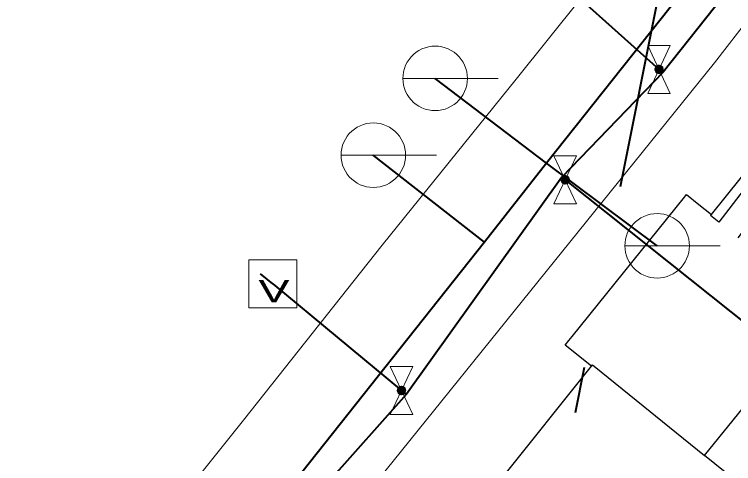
# Model space of a CAD drawing. Extents: x -968691 to -140888, y -1376050 to -879856.
# Drawn here: x -646150.75 to -646128.3, y -1062525.12 to -1062511.09 of the extents above; entities that cross this region are included whole.
import ezdxf
from ezdxf.enums import TextEntityAlignment as Align

# ---------------------------------------------------------------- set-up
doc = ezdxf.new("R2010")
doc.units = 0
doc.header["$LTSCALE"] = 4.8
for name, pattern in [('DASH_DOUBLE_DOT', [9.2, 5, -1.2, 0.3, -1.2, 0.3, -1.2]), ('DOTTED', [1.5, 0.3, -1.2]), ('LONG_DASHED', [7.5, 6, -1.5]), ('MEDIUM_DASHED', [4.5, 3, -1.5])]:
    doc.linetypes.add(name, pattern=pattern)
doc.layers.add('1', color=7, linetype='Continuous', lineweight=13)

msp = doc.modelspace()

# ---------------------------------------------------------------- hatches: boundary and pattern name
at = {"layer": '1'}
for points in [[(-646130.498, -1062512.81), (-646130.5, -1062512.786), (-646130.507, -1062512.763), (-646130.517, -1062512.741), (-646130.531, -1062512.722), (-646130.549, -1062512.705), (-646130.569, -1062512.692), (-646130.592, -1062512.683), (-646130.615, -1062512.679), (-646130.639, -1062512.678), (-646130.663, -1062512.682), (-646130.686, -1062512.69), (-646130.707, -1062512.702), (-646130.725, -1062512.718), (-646130.74, -1062512.737), (-646130.752, -1062512.758), (-646130.759, -1062512.781), (-646130.762, -1062512.805), (-646130.761, -1062512.829), (-646130.755, -1062512.852), (-646130.745, -1062512.874), (-646130.732, -1062512.894), (-646130.715, -1062512.911), (-646130.695, -1062512.925), (-646130.673, -1062512.935), (-646130.65, -1062512.941), (-646130.626, -1062512.942), (-646130.602, -1062512.939), (-646130.579, -1062512.932), (-646130.558, -1062512.921), (-646130.539, -1062512.906), (-646130.523, -1062512.887), (-646130.511, -1062512.867), (-646130.502, -1062512.844), (-646130.498, -1062512.82)], [(-646133.428, -1062516.26), (-646133.43, -1062516.236), (-646133.437, -1062516.213), (-646133.447, -1062516.191), (-646133.461, -1062516.172), (-646133.479, -1062516.155), (-646133.499, -1062516.142), (-646133.522, -1062516.133), (-646133.545, -1062516.129), (-646133.569, -1062516.128), (-646133.593, -1062516.132), (-646133.616, -1062516.14), (-646133.637, -1062516.152), (-646133.655, -1062516.168), (-646133.67, -1062516.187), (-646133.682, -1062516.208), (-646133.689, -1062516.231), (-646133.692, -1062516.255), (-646133.691, -1062516.279), (-646133.685, -1062516.302), (-646133.675, -1062516.324), (-646133.662, -1062516.344), (-646133.645, -1062516.361), (-646133.625, -1062516.375), (-646133.603, -1062516.385), (-646133.58, -1062516.391), (-646133.556, -1062516.392), (-646133.532, -1062516.389), (-646133.509, -1062516.382), (-646133.488, -1062516.371), (-646133.469, -1062516.356), (-646133.453, -1062516.337), (-646133.441, -1062516.317), (-646133.432, -1062516.294), (-646133.428, -1062516.27)], [(-646138.538, -1062522.84), (-646138.54, -1062522.816), (-646138.547, -1062522.793), (-646138.557, -1062522.771), (-646138.571, -1062522.752), (-646138.589, -1062522.735), (-646138.609, -1062522.722), (-646138.632, -1062522.713), (-646138.655, -1062522.709), (-646138.679, -1062522.708), (-646138.703, -1062522.712), (-646138.726, -1062522.72), (-646138.747, -1062522.732), (-646138.765, -1062522.748), (-646138.78, -1062522.767), (-646138.792, -1062522.788), (-646138.799, -1062522.811), (-646138.802, -1062522.835), (-646138.801, -1062522.859), (-646138.795, -1062522.882), (-646138.785, -1062522.904), (-646138.772, -1062522.924), (-646138.755, -1062522.941), (-646138.735, -1062522.955), (-646138.713, -1062522.965), (-646138.69, -1062522.971), (-646138.666, -1062522.972), (-646138.642, -1062522.969), (-646138.619, -1062522.962), (-646138.598, -1062522.951), (-646138.579, -1062522.936), (-646138.563, -1062522.917), (-646138.551, -1062522.897), (-646138.542, -1062522.874), (-646138.538, -1062522.85)]]:
    msp.add_hatch(color=256, dxfattribs=at).paths.add_polyline_path(points)

# ---------------------------------------------------------------- linework, layer by layer
for p, q in [((-646135.09, -1062513.113), (-646120.7, -1062495.06)), ((-646128.903, -1062512.606), (-646125.112, -1062507.701)), ((-646134.64, -1062509.22), (-646130.63, -1062512.81)), ((-646140.11, -1062526.51), (-646128.903, -1062512.606)), ((-646130.5, -1062512.9), (-646130.63, -1062512.81)), ((-646138.628, -1062513.09), (-646135.652, -1062513.09)), ((-646134.145, -1062515.74), (-646137.62, -1062513.09)), ((-646140.558, -1062515.49), (-646137.582, -1062515.49)), ((-646136.081, -1062518.202), (-646139.55, -1062515.49)), ((-646130.69, -1062518.32), (-646134.145, -1062515.74)), ((-646133.66, -1062516.18), (-646133.56, -1062516.26)), ((-646133.56, -1062516.26), (-646126.607, -1062521.806)), ((-646131.698, -1062518.32), (-646128.722, -1062518.32)), ((-646142.69, -1062519.51), (-646143.075, -1062519.191)), ((-646142.69, -1062519.51), (-646138.67, -1062522.84)), ((-646138.51, -1062522.95), (-646138.67, -1062522.84)), ((-646150.754, -1062532.695), (-646143.6, -1062523.77))]:
    msp.add_line(p, q, dxfattribs=at)
at = {"layer": '1', "linetype": 'DASH_DOUBLE_DOT', "lineweight": 40}
msp.add_line((-646149.08, -1062603.085), (-646128.34, -1062498.95), dxfattribs=at)
at = {"layer": '1', "linetype": 'LONG_DASHED', "lineweight": 40}
for p, q in [((-646124.36, -1062505.11), (-646130.5, -1062512.9)), ((-646134.64, -1062509.22), (-646130.63, -1062512.81)), ((-646130.5, -1062512.9), (-646133.66, -1062516.18)), ((-646130.5, -1062512.9), (-646130.63, -1062512.81)), ((-646134.145, -1062515.74), (-646137.62, -1062513.09)), ((-646136.081, -1062518.202), (-646139.55, -1062515.49)), ((-646130.69, -1062518.32), (-646134.145, -1062515.74)), ((-646133.66, -1062516.18), (-646138.51, -1062522.95)), ((-646133.66, -1062516.18), (-646133.56, -1062516.26)), ((-646133.56, -1062516.26), (-646126.607, -1062521.806)), ((-646142.69, -1062519.51), (-646138.67, -1062522.84)), ((-646138.51, -1062522.95), (-646138.67, -1062522.84)), ((-646138.51, -1062522.95), (-646141.97, -1062526.84))]:
    msp.add_line(p, q, dxfattribs=at)
at = {"layer": '1', "lineweight": 35}
for p, q in [((-646124.36, -1062505.11), (-646130.5, -1062512.9)), ((-646130.5, -1062512.9), (-646133.66, -1062516.18)), ((-646133.66, -1062516.18), (-646138.51, -1062522.95)), ((-646138.51, -1062522.95), (-646141.97, -1062526.84))]:
    msp.add_line(p, q, dxfattribs=at)
at = {"layer": '1', "linetype": 'MEDIUM_DASHED', "lineweight": 25}
for p, q in [((-646129.839, -1062516.805), (-646129.77, -1062516.72)), ((-646129.77, -1062516.72), (-646129.388, -1062517.026)), ((-646129.388, -1062517.026), (-646128.996, -1062517.34)), ((-646132.738, -1062522.076), (-646133.56, -1062521.42))]:
    msp.add_line(p, q, dxfattribs=at)
at = {"layer": '1', "linetype": 'DOTTED', "lineweight": 40}
msp.add_line((-646142.69, -1062519.51), (-646143.075, -1062519.191), dxfattribs=at)
at = {"layer": '1', "lineweight": 25}
for p, q in [((-646137.711, -1062528.301), (-646132.738, -1062522.076)), ((-646132.738, -1062522.076), (-646132.71, -1062522.04)), ((-646132.71, -1062522.04), (-646132.441, -1062522.257)), ((-646132.441, -1062522.257), (-646129.21, -1062524.87))]:
    msp.add_line(p, q, dxfattribs=at)
at = {"layer": '1', "linetype": 'LONG_DASHED', "lineweight": 40}
msp.add_lwpolyline([(-646125.463, -1062504.79), (-646134.145, -1062515.74), (-646136.081, -1062518.202), (-646142.83, -1062526.728), (-646149.07, -1062534.61)], dxfattribs=at)
at = {"layer": '1', "lineweight": 35}
msp.add_lwpolyline([(-646125.463, -1062504.79), (-646134.145, -1062515.74), (-646136.081, -1062518.202), (-646142.83, -1062526.728), (-646149.07, -1062534.61)], dxfattribs=at)
at = {"layer": '1', "lineweight": 25}
for points in [[(-646128.16, -1062518.07), (-646127.4, -1062517.07), (-646128, -1062516.59), (-646128.76, -1062517.58), (-646129.02, -1062517.37), (-646128.996, -1062517.34), (-646126.74, -1062514.527), (-646124.033, -1062511.151), (-646124, -1062511.11)], [(-646124.91, -1062528.34), (-646129.21, -1062524.87), (-646125.45, -1062520.24)]]:
    msp.add_lwpolyline(points, dxfattribs=at)
at = {"layer": '1'}
for points in [[(-646130.98, -1062512.06), (-646130.28, -1062512.06), (-646130.98, -1062513.56), (-646130.28, -1062513.56)], [(-646137.62, -1062512.082), (-646137.725, -1062512.088), (-646137.829, -1062512.104), (-646137.931, -1062512.132), (-646138.03, -1062512.17), (-646138.124, -1062512.217), (-646138.212, -1062512.275), (-646138.294, -1062512.341), (-646138.369, -1062512.416), (-646138.435, -1062512.498), (-646138.493, -1062512.586), (-646138.54, -1062512.68), (-646138.578, -1062512.779), (-646138.606, -1062512.881), (-646138.622, -1062512.985), (-646138.628, -1062513.09), (-646138.622, -1062513.195), (-646138.606, -1062513.3), (-646138.578, -1062513.402), (-646138.54, -1062513.5), (-646138.493, -1062513.594), (-646138.435, -1062513.683), (-646138.369, -1062513.765), (-646138.294, -1062513.839), (-646138.212, -1062513.905), (-646138.124, -1062513.963), (-646138.03, -1062514.011), (-646137.931, -1062514.049), (-646137.829, -1062514.076), (-646137.725, -1062514.092), (-646137.62, -1062514.098), (-646137.515, -1062514.092), (-646137.41, -1062514.076), (-646137.308, -1062514.049), (-646137.21, -1062514.011), (-646137.116, -1062513.963), (-646137.027, -1062513.905), (-646136.945, -1062513.839), (-646136.871, -1062513.765), (-646136.805, -1062513.683), (-646136.747, -1062513.594), (-646136.699, -1062513.5), (-646136.661, -1062513.402), (-646136.634, -1062513.3), (-646136.618, -1062513.195), (-646136.612, -1062513.09), (-646136.618, -1062512.985), (-646136.634, -1062512.881), (-646136.661, -1062512.779), (-646136.699, -1062512.68), (-646136.747, -1062512.586), (-646136.805, -1062512.498), (-646136.871, -1062512.416), (-646136.945, -1062512.341), (-646137.027, -1062512.275), (-646137.116, -1062512.217), (-646137.21, -1062512.17), (-646137.308, -1062512.132), (-646137.41, -1062512.104), (-646137.515, -1062512.088)], [(-646130.498, -1062512.81), (-646130.5, -1062512.786), (-646130.507, -1062512.763), (-646130.517, -1062512.741), (-646130.531, -1062512.722), (-646130.549, -1062512.705), (-646130.569, -1062512.692), (-646130.592, -1062512.683), (-646130.615, -1062512.679), (-646130.639, -1062512.678), (-646130.663, -1062512.682), (-646130.686, -1062512.69), (-646130.707, -1062512.702), (-646130.725, -1062512.718), (-646130.74, -1062512.737), (-646130.752, -1062512.758), (-646130.759, -1062512.781), (-646130.762, -1062512.805), (-646130.761, -1062512.829), (-646130.755, -1062512.852), (-646130.745, -1062512.874), (-646130.732, -1062512.894), (-646130.715, -1062512.911), (-646130.695, -1062512.925), (-646130.673, -1062512.935), (-646130.65, -1062512.941), (-646130.626, -1062512.942), (-646130.602, -1062512.939), (-646130.579, -1062512.932), (-646130.558, -1062512.921), (-646130.539, -1062512.906), (-646130.523, -1062512.887), (-646130.511, -1062512.867), (-646130.502, -1062512.844), (-646130.498, -1062512.82)], [(-646139.55, -1062514.482), (-646139.655, -1062514.488), (-646139.759, -1062514.504), (-646139.861, -1062514.532), (-646139.96, -1062514.57), (-646140.054, -1062514.617), (-646140.142, -1062514.675), (-646140.224, -1062514.741), (-646140.299, -1062514.816), (-646140.365, -1062514.898), (-646140.423, -1062514.986), (-646140.47, -1062515.08), (-646140.508, -1062515.179), (-646140.536, -1062515.281), (-646140.552, -1062515.385), (-646140.558, -1062515.49), (-646140.552, -1062515.595), (-646140.536, -1062515.7), (-646140.508, -1062515.802), (-646140.47, -1062515.9), (-646140.423, -1062515.994), (-646140.365, -1062516.083), (-646140.299, -1062516.165), (-646140.224, -1062516.239), (-646140.142, -1062516.305), (-646140.054, -1062516.363), (-646139.96, -1062516.411), (-646139.861, -1062516.449), (-646139.759, -1062516.476), (-646139.655, -1062516.492), (-646139.55, -1062516.498), (-646139.445, -1062516.492), (-646139.34, -1062516.476), (-646139.238, -1062516.449), (-646139.14, -1062516.411), (-646139.046, -1062516.363), (-646138.957, -1062516.305), (-646138.875, -1062516.239), (-646138.801, -1062516.165), (-646138.735, -1062516.083), (-646138.677, -1062515.994), (-646138.629, -1062515.9), (-646138.591, -1062515.802), (-646138.564, -1062515.7), (-646138.548, -1062515.595), (-646138.542, -1062515.49), (-646138.548, -1062515.385), (-646138.564, -1062515.281), (-646138.591, -1062515.179), (-646138.629, -1062515.08), (-646138.677, -1062514.986), (-646138.735, -1062514.898), (-646138.801, -1062514.816), (-646138.875, -1062514.741), (-646138.957, -1062514.675), (-646139.046, -1062514.617), (-646139.14, -1062514.57), (-646139.238, -1062514.532), (-646139.34, -1062514.504), (-646139.445, -1062514.488)], [(-646133.91, -1062515.51), (-646133.21, -1062515.51), (-646133.91, -1062517.01), (-646133.21, -1062517.01)], [(-646133.428, -1062516.26), (-646133.43, -1062516.236), (-646133.437, -1062516.213), (-646133.447, -1062516.191), (-646133.461, -1062516.172), (-646133.479, -1062516.155), (-646133.499, -1062516.142), (-646133.522, -1062516.133), (-646133.545, -1062516.129), (-646133.569, -1062516.128), (-646133.593, -1062516.132), (-646133.616, -1062516.14), (-646133.637, -1062516.152), (-646133.655, -1062516.168), (-646133.67, -1062516.187), (-646133.682, -1062516.208), (-646133.689, -1062516.231), (-646133.692, -1062516.255), (-646133.691, -1062516.279), (-646133.685, -1062516.302), (-646133.675, -1062516.324), (-646133.662, -1062516.344), (-646133.645, -1062516.361), (-646133.625, -1062516.375), (-646133.603, -1062516.385), (-646133.58, -1062516.391), (-646133.556, -1062516.392), (-646133.532, -1062516.389), (-646133.509, -1062516.382), (-646133.488, -1062516.371), (-646133.469, -1062516.356), (-646133.453, -1062516.337), (-646133.441, -1062516.317), (-646133.432, -1062516.294), (-646133.428, -1062516.27)], [(-646130.69, -1062517.312), (-646130.795, -1062517.318), (-646130.899, -1062517.334), (-646131.001, -1062517.362), (-646131.1, -1062517.4), (-646131.194, -1062517.447), (-646131.282, -1062517.505), (-646131.364, -1062517.571), (-646131.439, -1062517.646), (-646131.505, -1062517.728), (-646131.563, -1062517.816), (-646131.61, -1062517.91), (-646131.648, -1062518.009), (-646131.676, -1062518.111), (-646131.692, -1062518.215), (-646131.698, -1062518.32), (-646131.692, -1062518.425), (-646131.676, -1062518.53), (-646131.648, -1062518.632), (-646131.61, -1062518.73), (-646131.563, -1062518.824), (-646131.505, -1062518.913), (-646131.439, -1062518.995), (-646131.364, -1062519.069), (-646131.282, -1062519.135), (-646131.194, -1062519.193), (-646131.1, -1062519.241), (-646131.001, -1062519.279), (-646130.899, -1062519.306), (-646130.795, -1062519.322), (-646130.69, -1062519.328), (-646130.585, -1062519.322), (-646130.48, -1062519.306), (-646130.378, -1062519.279), (-646130.28, -1062519.241), (-646130.186, -1062519.193), (-646130.097, -1062519.135), (-646130.015, -1062519.069), (-646129.941, -1062518.995), (-646129.875, -1062518.913), (-646129.817, -1062518.824), (-646129.769, -1062518.73), (-646129.731, -1062518.632), (-646129.704, -1062518.53), (-646129.688, -1062518.425), (-646129.682, -1062518.32), (-646129.688, -1062518.215), (-646129.704, -1062518.111), (-646129.731, -1062518.009), (-646129.769, -1062517.91), (-646129.817, -1062517.816), (-646129.875, -1062517.728), (-646129.941, -1062517.646), (-646130.015, -1062517.571), (-646130.097, -1062517.505), (-646130.186, -1062517.447), (-646130.28, -1062517.4), (-646130.378, -1062517.362), (-646130.48, -1062517.334), (-646130.585, -1062517.318)], [(-646143.44, -1062520.26), (-646141.94, -1062520.26), (-646141.94, -1062518.76), (-646143.44, -1062518.76)], [(-646139.02, -1062522.09), (-646138.32, -1062522.09), (-646139.02, -1062523.59), (-646138.32, -1062523.59)], [(-646138.538, -1062522.84), (-646138.54, -1062522.816), (-646138.547, -1062522.793), (-646138.557, -1062522.771), (-646138.571, -1062522.752), (-646138.589, -1062522.735), (-646138.609, -1062522.722), (-646138.632, -1062522.713), (-646138.655, -1062522.709), (-646138.679, -1062522.708), (-646138.703, -1062522.712), (-646138.726, -1062522.72), (-646138.747, -1062522.732), (-646138.765, -1062522.748), (-646138.78, -1062522.767), (-646138.792, -1062522.788), (-646138.799, -1062522.811), (-646138.802, -1062522.835), (-646138.801, -1062522.859), (-646138.795, -1062522.882), (-646138.785, -1062522.904), (-646138.772, -1062522.924), (-646138.755, -1062522.941), (-646138.735, -1062522.955), (-646138.713, -1062522.965), (-646138.69, -1062522.971), (-646138.666, -1062522.972), (-646138.642, -1062522.969), (-646138.619, -1062522.962), (-646138.598, -1062522.951), (-646138.579, -1062522.936), (-646138.563, -1062522.917), (-646138.551, -1062522.897), (-646138.542, -1062522.874), (-646138.538, -1062522.85)]]:
    msp.add_lwpolyline(points, close=True, dxfattribs=at)
msp.add_lwpolyline([(-646143.6, -1062523.77), (-646139.276, -1062518.3), (-646135.09, -1062513.113)], dxfattribs=at)
at = {"layer": '1', "linetype": 'MEDIUM_DASHED', "lineweight": 25}
msp.add_lwpolyline([(-646133.56, -1062521.42), (-646133.444, -1062521.277), (-646133.341, -1062521.149), (-646129.839, -1062516.805)], dxfattribs=at)

# ---------------------------------------------------------------- texts
at = {"layer": '1', "width": 1.55}
msp.add_text('V', height=0.7, dxfattribs=at).set_placement((-646142.651, -1062520.089), align=Align.CENTER)

doc.saveas('drawing.dxf')
